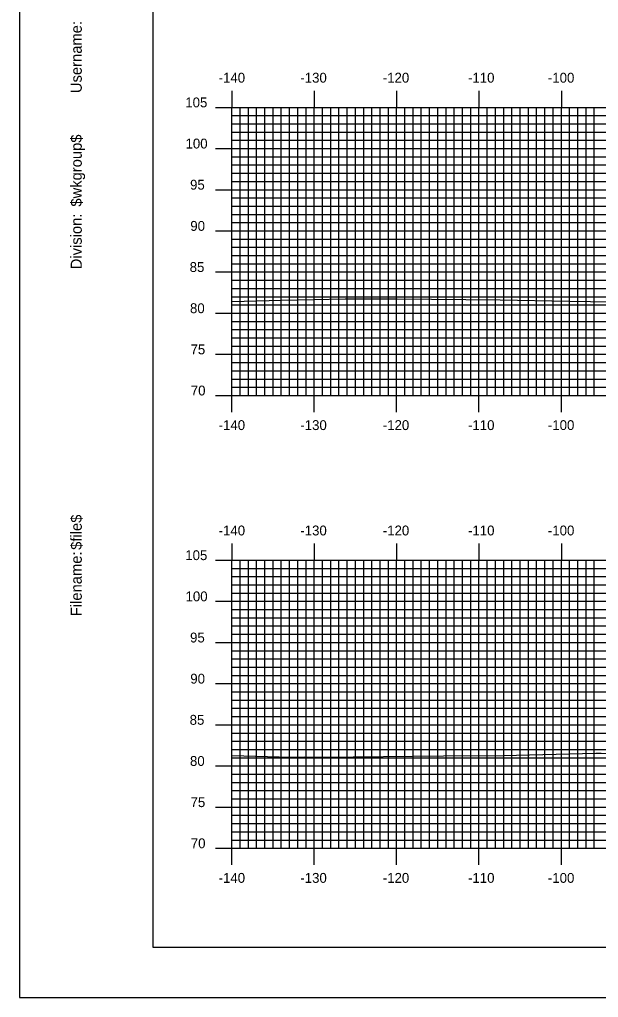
# Model space of a CAD drawing. Extents: x 853329 to 853673, y 364366 to 364586.
# Drawn here: x 853329.4 to 853399.7, y 364365.7 to 364484.5 of the extents above; entities that cross this region are included whole.
import ezdxf

# ---------------------------------------------------------------- set-up
doc = ezdxf.new("R2010")
doc.units = 0
for name, color, linetype in [('BORDER', 7, 'Continuous'), ('H_V ANNOTATION', 7, 'Continuous'), ('MAJOR', 7, 'Continuous'), ('MINOR', 7, 'Continuous'), ('PLOT BOUNDARY', 7, 'Continuous'), ('S_Roadway_Centerline', 7, 'Continuous')]:
    doc.layers.add(name, color=color, linetype=linetype)

msp = doc.modelspace()

# ---------------------------------------------------------------- linework, layer by layer
at = {"layer": 'BORDER'}
msp.add_lwpolyline([(853345.6, 364371.79), (853665.6, 364371.79), (853665.6, 364581.79), (853345.6, 364581.79)], close=True, dxfattribs=at)
at = {"layer": 'MAJOR'}
for p, q in [((853355.2, 364475.79), (853355.2, 364473.79)), ((853365.2, 364475.79), (853365.2, 364473.79)), ((853375.2, 364475.79), (853375.2, 364473.79)), ((853385.2, 364475.79), (853385.2, 364473.79)), ((853395.2, 364475.79), (853395.2, 364473.79)), ((853353.2, 364473.79), (853355.2, 364473.79)), ((853355.2, 364473.79), (853635.2, 364473.79)), ((853355.2, 364438.79), (853355.2, 364473.79)), ((853355.2, 364438.79), (853355.2, 364473.79)), ((853355.2, 364473.79), (853635.2, 364473.79)), ((853365.2, 364438.79), (853365.2, 364473.79)), ((853375.2, 364438.79), (853375.2, 364473.79)), ((853385.2, 364438.79), (853385.2, 364473.79)), ((853395.2, 364438.79), (853395.2, 364473.79)), ((853353.2, 364468.79), (853355.2, 364468.79)), ((853355.2, 364468.79), (853635.2, 364468.79)), ((853353.2, 364463.79), (853355.2, 364463.79)), ((853355.2, 364463.79), (853635.2, 364463.79)), ((853353.2, 364458.79), (853355.2, 364458.79)), ((853355.2, 364458.79), (853635.2, 364458.79)), ((853353.2, 364453.79), (853355.2, 364453.79)), ((853355.2, 364453.79), (853635.2, 364453.79)), ((853353.2, 364448.79), (853355.2, 364448.79)), ((853355.2, 364448.79), (853635.2, 364448.79)), ((853353.2, 364443.79), (853355.2, 364443.79)), ((853355.2, 364443.79), (853635.2, 364443.79)), ((853353.2, 364438.79), (853355.2, 364438.79)), ((853355.2, 364438.79), (853635.2, 364438.79)), ((853355.2, 364438.79), (853635.2, 364438.79)), ((853355.2, 364436.78), (853355.2, 364438.79)), ((853365.2, 364436.78), (853365.2, 364438.79)), ((853375.2, 364436.78), (853375.2, 364438.79)), ((853385.2, 364436.78), (853385.2, 364438.79)), ((853395.2, 364436.78), (853395.2, 364438.79)), ((853355.2, 364420.79), (853355.2, 364418.79)), ((853365.2, 364420.79), (853365.2, 364418.79)), ((853375.2, 364420.79), (853375.2, 364418.79)), ((853385.2, 364420.79), (853385.2, 364418.79)), ((853395.2, 364420.79), (853395.2, 364418.79)), ((853353.2, 364418.79), (853355.2, 364418.79)), ((853355.2, 364418.79), (853635.2, 364418.79)), ((853355.2, 364383.79), (853355.2, 364418.79)), ((853355.2, 364383.79), (853355.2, 364418.79)), ((853355.2, 364418.79), (853635.2, 364418.79)), ((853365.2, 364383.79), (853365.2, 364418.79)), ((853375.2, 364383.79), (853375.2, 364418.79)), ((853385.2, 364383.79), (853385.2, 364418.79)), ((853395.2, 364383.79), (853395.2, 364418.79)), ((853353.2, 364413.79), (853355.2, 364413.79)), ((853355.2, 364413.79), (853635.2, 364413.79)), ((853353.2, 364408.79), (853355.2, 364408.79)), ((853355.2, 364408.79), (853635.2, 364408.79)), ((853353.2, 364403.79), (853355.2, 364403.79)), ((853355.2, 364403.79), (853635.2, 364403.79)), ((853353.2, 364398.79), (853355.2, 364398.79)), ((853355.2, 364398.79), (853635.2, 364398.79)), ((853353.2, 364393.79), (853355.2, 364393.79)), ((853355.2, 364393.79), (853635.2, 364393.79)), ((853353.2, 364388.79), (853355.2, 364388.79)), ((853355.2, 364388.79), (853635.2, 364388.79)), ((853353.2, 364383.79), (853355.2, 364383.79)), ((853355.2, 364383.79), (853635.2, 364383.79)), ((853355.2, 364383.79), (853635.2, 364383.79)), ((853355.2, 364381.78), (853355.2, 364383.79)), ((853365.2, 364381.78), (853365.2, 364383.79)), ((853375.2, 364381.78), (853375.2, 364383.79)), ((853385.2, 364381.78), (853385.2, 364383.79)), ((853395.2, 364381.78), (853395.2, 364383.79))]:
    msp.add_line(p, q, dxfattribs=at)
at = {"layer": 'MINOR'}
for p, q in [((853356.2, 364438.79), (853356.2, 364473.79)), ((853357.2, 364438.79), (853357.2, 364473.79)), ((853358.2, 364438.79), (853358.2, 364473.79)), ((853359.2, 364438.79), (853359.2, 364473.79)), ((853360.2, 364438.79), (853360.2, 364473.79)), ((853361.2, 364438.79), (853361.2, 364473.79)), ((853362.2, 364438.79), (853362.2, 364473.79)), ((853363.2, 364438.79), (853363.2, 364473.79)), ((853364.2, 364438.79), (853364.2, 364473.79)), ((853366.2, 364438.79), (853366.2, 364473.79)), ((853367.2, 364438.79), (853367.2, 364473.79)), ((853368.2, 364438.79), (853368.2, 364473.79)), ((853369.2, 364438.79), (853369.2, 364473.79)), ((853370.2, 364438.79), (853370.2, 364473.79)), ((853371.2, 364438.79), (853371.2, 364473.79)), ((853372.2, 364438.79), (853372.2, 364473.79)), ((853373.2, 364438.79), (853373.2, 364473.79)), ((853374.2, 364438.79), (853374.2, 364473.79)), ((853376.2, 364438.79), (853376.2, 364473.79)), ((853377.2, 364438.79), (853377.2, 364473.79)), ((853378.2, 364438.79), (853378.2, 364473.79)), ((853379.2, 364438.79), (853379.2, 364473.79)), ((853380.2, 364438.79), (853380.2, 364473.79)), ((853381.2, 364438.79), (853381.2, 364473.79)), ((853382.2, 364438.79), (853382.2, 364473.79)), ((853383.2, 364438.79), (853383.2, 364473.79)), ((853384.2, 364438.79), (853384.2, 364473.79)), ((853386.2, 364438.79), (853386.2, 364473.79)), ((853387.2, 364438.79), (853387.2, 364473.79)), ((853388.2, 364438.79), (853388.2, 364473.79)), ((853389.2, 364438.79), (853389.2, 364473.79)), ((853390.2, 364438.79), (853390.2, 364473.79)), ((853391.2, 364438.79), (853391.2, 364473.79)), ((853392.2, 364438.79), (853392.2, 364473.79)), ((853393.2, 364438.79), (853393.2, 364473.79)), ((853394.2, 364438.79), (853394.2, 364473.79)), ((853396.2, 364438.79), (853396.2, 364473.79)), ((853397.2, 364438.79), (853397.2, 364473.79)), ((853398.2, 364438.79), (853398.2, 364473.79)), ((853399.2, 364438.79), (853399.2, 364473.79)), ((853355.2, 364472.79), (853635.2, 364472.79)), ((853355.2, 364472.79), (853357.21, 364472.79)), ((853355.2, 364471.79), (853635.2, 364471.79)), ((853355.2, 364471.79), (853357.21, 364471.79)), ((853355.2, 364470.79), (853635.2, 364470.79)), ((853355.2, 364470.79), (853357.21, 364470.79)), ((853355.2, 364469.79), (853635.2, 364469.79)), ((853355.2, 364469.79), (853357.21, 364469.79)), ((853355.2, 364467.79), (853635.2, 364467.79)), ((853355.2, 364467.79), (853357.21, 364467.79)), ((853355.2, 364466.79), (853635.2, 364466.79)), ((853355.2, 364466.79), (853357.21, 364466.79)), ((853355.2, 364465.79), (853635.2, 364465.79)), ((853355.2, 364465.79), (853357.21, 364465.79)), ((853355.2, 364464.79), (853635.2, 364464.79)), ((853355.2, 364464.79), (853357.21, 364464.79)), ((853355.2, 364462.79), (853635.2, 364462.79)), ((853355.2, 364462.79), (853357.21, 364462.79)), ((853355.2, 364461.79), (853635.2, 364461.79)), ((853355.2, 364461.79), (853357.21, 364461.79)), ((853355.2, 364460.79), (853635.2, 364460.79)), ((853355.2, 364460.79), (853357.21, 364460.79)), ((853355.2, 364459.79), (853635.2, 364459.79)), ((853355.2, 364459.79), (853357.21, 364459.79)), ((853355.2, 364457.79), (853635.2, 364457.79)), ((853355.2, 364457.79), (853357.21, 364457.79)), ((853355.2, 364456.79), (853635.2, 364456.79)), ((853355.2, 364456.79), (853357.21, 364456.79)), ((853355.2, 364455.79), (853635.2, 364455.79)), ((853355.2, 364455.79), (853357.21, 364455.79)), ((853355.2, 364454.79), (853635.2, 364454.79)), ((853355.2, 364454.79), (853357.21, 364454.79)), ((853355.2, 364452.79), (853635.2, 364452.79)), ((853355.2, 364452.79), (853357.21, 364452.79)), ((853355.2, 364451.79), (853635.2, 364451.79)), ((853355.2, 364451.79), (853357.21, 364451.79)), ((853355.2, 364450.79), (853635.2, 364450.79)), ((853355.2, 364450.79), (853357.21, 364450.79)), ((853355.2, 364449.79), (853635.2, 364449.79)), ((853355.2, 364449.79), (853357.21, 364449.79)), ((853355.2, 364447.79), (853635.2, 364447.79)), ((853355.2, 364447.79), (853357.21, 364447.79)), ((853355.2, 364446.79), (853635.2, 364446.79)), ((853355.2, 364446.79), (853357.21, 364446.79)), ((853355.2, 364445.79), (853635.2, 364445.79)), ((853355.2, 364445.79), (853357.21, 364445.79)), ((853355.2, 364444.79), (853635.2, 364444.79)), ((853355.2, 364444.79), (853357.21, 364444.79)), ((853355.2, 364442.79), (853635.2, 364442.79)), ((853355.2, 364442.79), (853357.21, 364442.79)), ((853355.2, 364441.79), (853635.2, 364441.79)), ((853355.2, 364441.79), (853357.21, 364441.79)), ((853355.2, 364440.79), (853635.2, 364440.79)), ((853355.2, 364440.79), (853357.21, 364440.79)), ((853355.2, 364439.79), (853635.2, 364439.79)), ((853355.2, 364439.79), (853357.21, 364439.79)), ((853355.2, 364417.79), (853635.2, 364417.79)), ((853355.2, 364417.79), (853357.21, 364417.79)), ((853356.2, 364383.79), (853356.2, 364418.79)), ((853357.2, 364383.79), (853357.2, 364418.79)), ((853358.2, 364383.79), (853358.2, 364418.79)), ((853359.2, 364383.79), (853359.2, 364418.79)), ((853360.2, 364383.79), (853360.2, 364418.79)), ((853361.2, 364383.79), (853361.2, 364418.79)), ((853362.2, 364383.79), (853362.2, 364418.79)), ((853363.2, 364383.79), (853363.2, 364418.79)), ((853364.2, 364383.79), (853364.2, 364418.79)), ((853366.2, 364383.79), (853366.2, 364418.79)), ((853367.2, 364383.79), (853367.2, 364418.79)), ((853368.2, 364383.79), (853368.2, 364418.79)), ((853369.2, 364383.79), (853369.2, 364418.79)), ((853370.2, 364383.79), (853370.2, 364418.79)), ((853371.2, 364383.79), (853371.2, 364418.79)), ((853372.2, 364383.79), (853372.2, 364418.79)), ((853373.2, 364383.79), (853373.2, 364418.79)), ((853374.2, 364383.79), (853374.2, 364418.79)), ((853376.2, 364383.79), (853376.2, 364418.79)), ((853377.2, 364383.79), (853377.2, 364418.79)), ((853378.2, 364383.79), (853378.2, 364418.79)), ((853379.2, 364383.79), (853379.2, 364418.79)), ((853380.2, 364383.79), (853380.2, 364418.79)), ((853381.2, 364383.79), (853381.2, 364418.79)), ((853382.2, 364383.79), (853382.2, 364418.79)), ((853383.2, 364383.79), (853383.2, 364418.79)), ((853384.2, 364383.79), (853384.2, 364418.79)), ((853386.2, 364383.79), (853386.2, 364418.79)), ((853387.2, 364383.79), (853387.2, 364418.79)), ((853388.2, 364383.79), (853388.2, 364418.79)), ((853389.2, 364383.79), (853389.2, 364418.79)), ((853390.2, 364383.79), (853390.2, 364418.79)), ((853391.2, 364383.79), (853391.2, 364418.79)), ((853392.2, 364383.79), (853392.2, 364418.79)), ((853393.2, 364383.79), (853393.2, 364418.79)), ((853394.2, 364383.79), (853394.2, 364418.79)), ((853396.2, 364383.79), (853396.2, 364418.79)), ((853397.2, 364383.79), (853397.2, 364418.79)), ((853398.2, 364383.79), (853398.2, 364418.79)), ((853399.2, 364383.79), (853399.2, 364418.79)), ((853355.2, 364416.79), (853635.2, 364416.79)), ((853355.2, 364416.79), (853357.21, 364416.79)), ((853355.2, 364415.79), (853635.2, 364415.79)), ((853355.2, 364415.79), (853357.21, 364415.79)), ((853355.2, 364414.79), (853635.2, 364414.79)), ((853355.2, 364414.79), (853357.21, 364414.79)), ((853355.2, 364412.79), (853635.2, 364412.79)), ((853355.2, 364412.79), (853357.21, 364412.79)), ((853355.2, 364411.79), (853635.2, 364411.79)), ((853355.2, 364411.79), (853357.21, 364411.79)), ((853355.2, 364410.79), (853635.2, 364410.79)), ((853355.2, 364410.79), (853357.21, 364410.79)), ((853355.2, 364409.79), (853635.2, 364409.79)), ((853355.2, 364409.79), (853357.21, 364409.79)), ((853355.2, 364407.79), (853635.2, 364407.79)), ((853355.2, 364407.79), (853357.21, 364407.79)), ((853355.2, 364406.79), (853635.2, 364406.79)), ((853355.2, 364406.79), (853357.21, 364406.79)), ((853355.2, 364405.79), (853635.2, 364405.79)), ((853355.2, 364405.79), (853357.21, 364405.79)), ((853355.2, 364404.79), (853635.2, 364404.79)), ((853355.2, 364404.79), (853357.21, 364404.79)), ((853355.2, 364402.79), (853635.2, 364402.79)), ((853355.2, 364402.79), (853357.21, 364402.79)), ((853355.2, 364401.79), (853635.2, 364401.79)), ((853355.2, 364401.79), (853357.21, 364401.79)), ((853355.2, 364400.79), (853635.2, 364400.79)), ((853355.2, 364400.79), (853357.21, 364400.79)), ((853355.2, 364399.79), (853635.2, 364399.79)), ((853355.2, 364399.79), (853357.21, 364399.79)), ((853355.2, 364397.79), (853635.2, 364397.79)), ((853355.2, 364397.79), (853357.21, 364397.79)), ((853355.2, 364396.79), (853635.2, 364396.79)), ((853355.2, 364396.79), (853357.21, 364396.79)), ((853355.2, 364395.79), (853635.2, 364395.79)), ((853355.2, 364395.79), (853357.21, 364395.79)), ((853355.2, 364394.79), (853635.2, 364394.79)), ((853355.2, 364394.79), (853357.21, 364394.79)), ((853355.2, 364392.79), (853635.2, 364392.79)), ((853355.2, 364392.79), (853357.21, 364392.79)), ((853355.2, 364391.79), (853635.2, 364391.79)), ((853355.2, 364391.79), (853357.21, 364391.79)), ((853355.2, 364390.79), (853635.2, 364390.79)), ((853355.2, 364390.79), (853357.21, 364390.79)), ((853355.2, 364389.79), (853635.2, 364389.79)), ((853355.2, 364389.79), (853357.21, 364389.79)), ((853355.2, 364387.79), (853635.2, 364387.79)), ((853355.2, 364387.79), (853357.21, 364387.79)), ((853355.2, 364386.79), (853635.2, 364386.79)), ((853355.2, 364386.79), (853357.21, 364386.79)), ((853355.2, 364385.79), (853635.2, 364385.79)), ((853355.2, 364385.79), (853357.21, 364385.79)), ((853355.2, 364384.79), (853635.2, 364384.79)), ((853355.2, 364384.79), (853357.21, 364384.79))]:
    msp.add_line(p, q, dxfattribs=at)
at = {"layer": 'PLOT BOUNDARY'}
msp.add_lwpolyline([(853329.42, 364365.67), (853669.42, 364365.67), (853669.42, 364585.67), (853329.42, 364585.67)], close=True, dxfattribs=at)
at = {"layer": 'S_Roadway_Centerline'}
for points in [[(853355.2, 364450.2), (853361.24, 364450.38), (853368.97, 364450.51), (853375.26, 364450.52), (853387.79, 364450.39), (853396.17, 364450.26), (853406.5, 364450.07), (853414.3, 364450.35), (853424.36, 364450.61), (853433.05, 364450.39), (853441.83, 364450.4), (853452.13, 364449.72), (853469.83, 364448.24)], [(853355.2, 364395.05), (853362.38, 364394.85), (853364, 364394.9), (853366.27, 364394.85), (853380.9, 364395), (853388.13, 364395.04), (853399.37, 364395.34), (853400.05, 364395.34), (853401.83, 364395.26), (853413.18, 364394.93), (853417.74, 364394.77), (853429.84, 364393.98), (853435.5, 364393.7), (853449.28, 364393.29), (853453.21, 364393.02), (853461.87, 364393.67), (853472.58, 364394.44)]]:
    msp.add_lwpolyline(points, dxfattribs=at)

# ---------------------------------------------------------------- texts
at = {"layer": 'BORDER'}
for s, p in [('Username:', (853336.97, 364475.52)), ('$wkgroup$', (853336.97, 364461.73)), ('Division:', (853336.97, 364454.12)), ('$file$', (853336.97, 364420.04)), ('Filename:', (853336.97, 364411.98))]:
    msp.add_text(s, height=1.339, rotation=90, dxfattribs=at).set_placement(p)
at = {"layer": 'H_V ANNOTATION'}
for s, p in [('-140', (853353.59, 364476.79)), ('-130', (853363.51, 364476.79)), ('-120', (853373.52, 364476.79)), ('-110', (853383.87, 364476.79)), ('-100', (853393.57, 364476.79)), ('105', (853349.54, 364473.79)), ('100', (853349.57, 364468.79)), ('95', (853350.12, 364463.79)), ('90', (853350.15, 364458.79)), ('85', (853350.07, 364453.79)), ('80', (853350.11, 364448.79)), ('75', (853350.18, 364443.79)), ('70', (853350.21, 364438.79)), ('-140', (853353.59, 364434.59)), ('-130', (853363.51, 364434.59)), ('-120', (853373.52, 364434.59)), ('-110', (853383.87, 364434.59)), ('-100', (853393.57, 364434.59)), ('-140', (853353.59, 364421.79)), ('-130', (853363.51, 364421.79)), ('-120', (853373.52, 364421.79)), ('-110', (853383.87, 364421.79)), ('-100', (853393.57, 364421.79)), ('105', (853349.54, 364418.79)), ('100', (853349.57, 364413.79)), ('95', (853350.12, 364408.79)), ('90', (853350.15, 364403.79)), ('85', (853350.07, 364398.79)), ('80', (853350.11, 364393.79)), ('75', (853350.18, 364388.79)), ('70', (853350.21, 364383.79)), ('-140', (853353.59, 364379.59)), ('-130', (853363.51, 364379.59)), ('-120', (853373.52, 364379.59)), ('-110', (853383.87, 364379.59)), ('-100', (853393.57, 364379.59))]:
    msp.add_text(s, height=1.2, dxfattribs=at).set_placement(p)
at = {"layer": 'MAJOR'}
for p in [(853355.2, 364438.79), (853355.2, 364383.79)]:
    msp.add_text('-', height=0.012, dxfattribs=at).set_placement(p)

doc.saveas('drawing.dxf')
